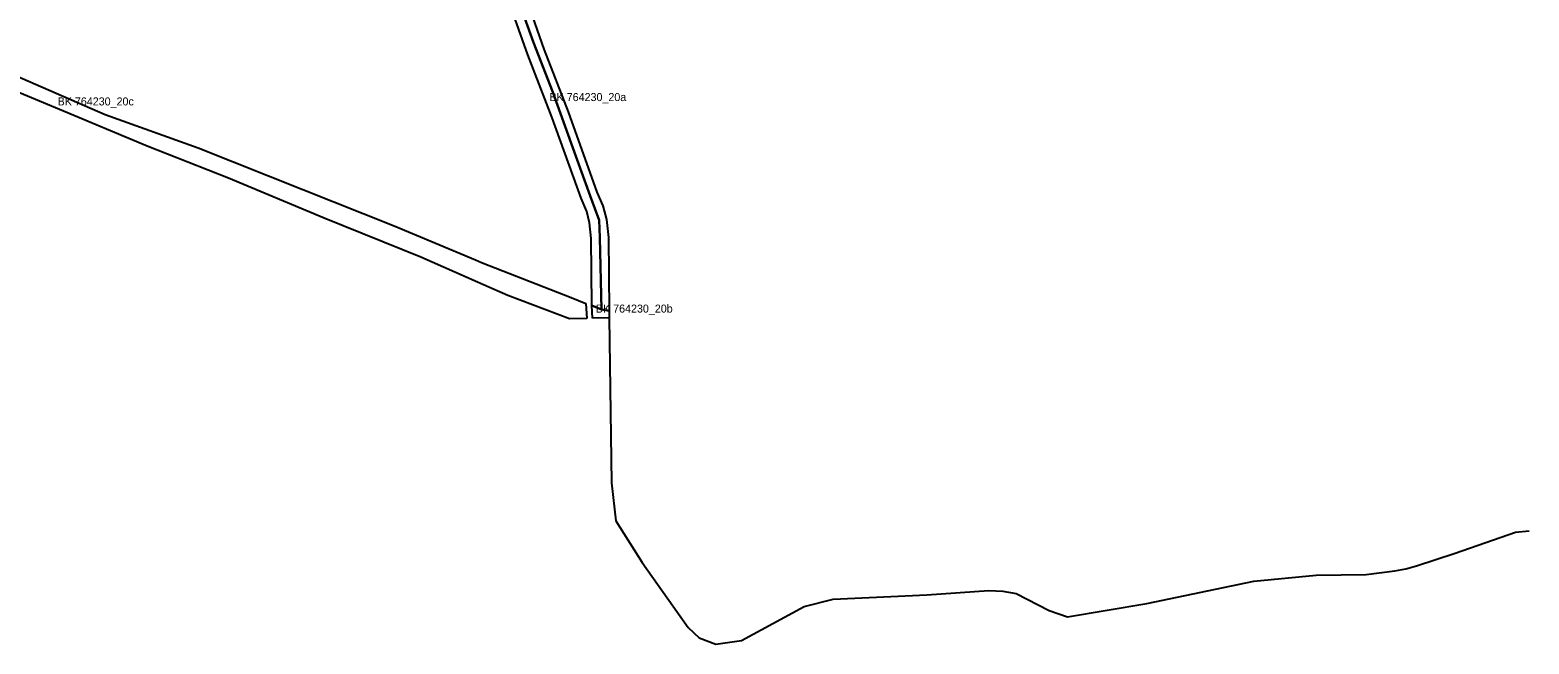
# Model space of a CAD drawing. Extents: x -521616 to -516782, y -1190061 to -1184927.
# Drawn here: x -519440 to -518129, y -1190061 to -1189525 of the extents above; entities that cross this region are included whole.
import ezdxf

# ---------------------------------------------------------------- set-up
doc = ezdxf.new("R2010")
doc.units = 0
for name, color, linetype in [('i_prvek_l_s', 7, 'Continuous'), ('LBK_n', 7, 'Continuous'), ('LBK_s', 7, 'Continuous')]:
    doc.layers.add(name, color=color, linetype=linetype)

msp = doc.modelspace()

# ---------------------------------------------------------------- linework, layer by layer
at = {"layer": 'i_prvek_l_s'}
msp.add_lwpolyline([(-518933.5, -1189776.3), (-518931.5, -1189920.7), (-518927.8, -1189953.9), (-518904.5, -1189990.3), (-518864.4, -1190047.1), (-518854.8, -1190056.1), (-518840.1, -1190061.5), (-518817.9, -1190058.4), (-518763.1, -1190028.8), (-518737.5, -1190022.4), (-518655.6, -1190018.4), (-518601.4, -1190014.7), (-518589.2, -1190015.2), (-518577.5, -1190017.2), (-518548.6, -1190032.2), (-518532.7, -1190037.7), (-518463.3, -1190026), (-518369.8, -1190006.7), (-518315.3, -1190001.3), (-518271.6, -1190000.8), (-518246.4, -1189997.4), (-518236.9, -1189995.7), (-518227.5, -1189993.1), (-518193.8, -1189982.2), (-518141, -1189963.6), (-518129.1, -1189962.6)], dxfattribs=at)
at = {"layer": 'LBK_n'}
msp.add_lwpolyline([(-519022.2, -1189473.1), (-518999.6, -1189535.6), (-518982.7, -1189579), (-518965.3, -1189627.9), (-518950, -1189669.6), (-518945.9, -1189680.7), (-518942.2, -1189690.9), (-518941.7, -1189706.3), (-518940.1, -1189769.1), (-518948.8, -1189765.7), (-518949.1, -1189707), (-518950.6, -1189693.2), (-518953.1, -1189683.5), (-518958.1, -1189671.9), (-518983.4, -1189601.6), (-519004.7, -1189546.6), (-519025, -1189488.9)], dxfattribs=at)
at = {"layer": 'LBK_s'}
for points in [[(-519010.8, -1189483.9), (-518990.6, -1189541.4), (-518969.3, -1189596.4), (-518944.2, -1189666.4), (-518938.9, -1189678.6), (-518935.8, -1189690.5), (-518934.1, -1189706.1), (-518933.6, -1189770.4), (-518940.1, -1189769.1), (-518941.7, -1189706.3), (-518942.2, -1189690.9), (-518945.9, -1189680.7), (-518950, -1189669.6), (-518965.3, -1189627.9), (-518982.7, -1189579), (-518999.6, -1189535.6), (-519022.2, -1189473.1)], [(-519048.5, -1189745.2), (-519098.2, -1189723.3), (-519182.6, -1189689.2), (-519266.4, -1189654.2), (-519337.4, -1189626.4), (-519414.2, -1189594.4), (-519509, -1189554.9)], [(-519459.8, -1189561.4), (-519374.1, -1189598.7), (-519292.9, -1189627.9), (-519201.4, -1189664.3), (-519121.6, -1189696.1), (-519050.3, -1189725.8)], [(-519050.3, -1189725.8), (-519045.2, -1189727.9), (-519045.1, -1189728)], [(-519045.1, -1189728), (-518966.8, -1189758.7), (-518953.8, -1189763.8)], [(-519043.3, -1189747.6), (-519048.5, -1189745.2)], [(-518953, -1189776.9), (-518968.2, -1189777.3), (-519022.1, -1189756.9), (-519043.3, -1189747.6)], [(-518953.8, -1189763.8), (-518953, -1189776.9)], [(-518948, -1189776.7), (-518948.8, -1189765.7)], [(-518948.8, -1189765.7), (-518940.1, -1189769.1), (-518933.6, -1189770.4), (-518933.5, -1189776.3), (-518948, -1189776.7)]]:
    msp.add_lwpolyline(points, dxfattribs=at)

# ---------------------------------------------------------------- texts
at = {"layer": 'LBK_n'}
msp.add_text('BK 764230_20a', height=7, dxfattribs=at).set_placement((-518985.7, -1189586.9))
at = {"layer": 'LBK_s'}
for s, p in [('BK 764230_20c', (-519415.8, -1189590.7)), ('BK 764230_20b', (-518945.1, -1189771.8))]:
    msp.add_text(s, height=7, dxfattribs=at).set_placement(p)

doc.saveas('drawing.dxf')
